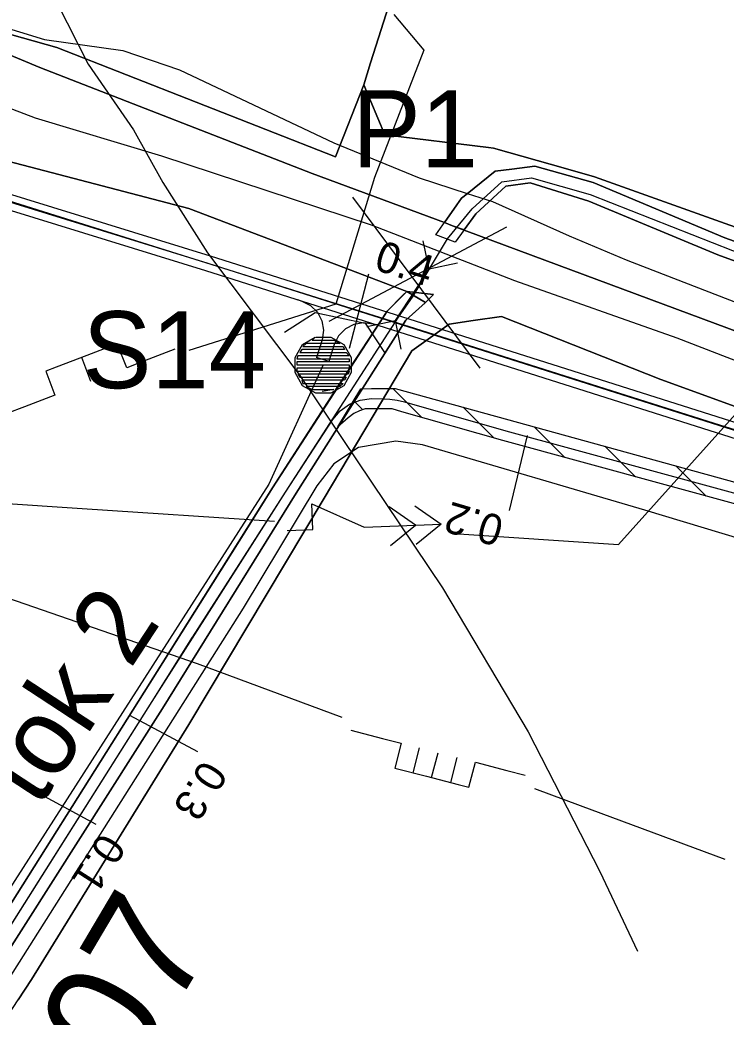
# Model space of a CAD drawing. Extents: x -645676 to -642474, y -1077513 to -1072613.
# Drawn here: x -645010.7 to -644873.3, y -1074904.3 to -1074710.1 of the extents above; entities that cross this region are included whole.
import ezdxf

# ---------------------------------------------------------------- set-up
doc = ezdxf.new("R2010")
doc.units = 0
for name, color, linetype in [('_elezni_n__tra_', 7, 'Continuous'), ('ELEKTRO', 7, 'Continuous'), ('KULTURY_STAV', 7, 'Continuous'), ('NOVY_STAV', 7, 'Continuous'), ('OSA', 7, 'Continuous'), ('PC_NAVRH', 7, 'Continuous'), ('PC_OBJ_POPIS_NAVRH', 7, 'Continuous'), ('PC_OBJ_POPIS_STAV', 7, 'Continuous'), ('PC_OBJEKTY_NAVRH', 7, 'Continuous'), ('PC_OBJEKTY_STAV', 7, 'Continuous'), ('PC_POPIS_NAVRH', 7, 'Continuous'), ('PC_STAN_NAVRH', 7, 'Continuous'), ('PLYNOVOD', 7, 'Continuous'), ('Ru_en__prvku_pr_zkumu', 7, 'Continuous'), ('SDELOVACI', 7, 'Continuous'), ('Vodn__plocha___navr_en_', 7, 'Continuous'), ('Vodn__plocha___st_vaj_c_', 7, 'Continuous'), ('Vodn__tok', 7, 'Continuous'), ('VRSTEVNICE', 7, 'Continuous')]:
    doc.layers.add(name, color=color, linetype=linetype)

# ---------------------------------------------------------------- blocks, each defined once
blk = doc.blocks.new('$406')
blk.add_lwpolyline([(-0.19, 0.72), (0.2, 0.72), (0.54, 0.53), (0.73, 0.19), (0.73, -0.2), (0.54, -0.54), (0.2, -0.73), (-0.19, -0.73), (-0.53, -0.54), (-0.72, -0.2), (-0.72, 0.19), (-0.53, 0.53), (-0.2, 0.72), (-0.28, 0.64), (0.28, 0.64), (0.44, 0.56), (-0.44, 0.56), (-0.52, 0.48), (0.52, 0.48), (0.56, 0.4), (-0.55, 0.4), (-0.6, 0.32), (0.6, 0.32), (0.68, 0.24), (-0.59, 0.24), (-0.65, 0.24), (-0.68, 0.16), (0.59, 0.16), (0.68, 0.16), (0.68, 0.08), (-0.59, 0.08), (-0.68, 0.08), (-0.68, 0), (0.59, 0), (0.68, 0), (0.68, -0.08), (-0.59, -0.08), (-0.68, -0.08), (-0.68, -0.16), (0.59, -0.16), (0.68, -0.16), (0.65, -0.24), (-0.62, -0.24), (-0.65, -0.24), (-0.6, -0.32), (0.6, -0.32), (0.56, -0.4), (-0.55, -0.4), (-0.52, -0.48), (0.52, -0.48), (0.44, -0.56), (-0.44, -0.56), (-0.28, -0.64), (0.28, -0.64), (-0.02, -0.69)])
blk = doc.blocks.new('$944')
blk.add_line((0, 1.5), (0, -1.5))
blk = doc.blocks.new('$938')
for p, q in [((-2, -0.8), (-1.2, 0)), ((2, -0.8), (1.2, 0))]:
    blk.add_line(p, q)
blk.add_lwpolyline([(-2, 0.8), (-1.2, 0), (1.2, 0), (2, 0.8)])
blk = doc.blocks.new('$935')
blk.add_lwpolyline([(-2, -1), (-1, 0), (1, 0), (2, -1)])
blk = doc.blocks.new('6$3320')
blk.add_line((0, 0), (0, -1))
blk.add_lwpolyline([(-3.5, 0), (-2.23, 0), (-1.5, 0), (-1.48, -1), (-0.21, -1), (1.06, -1), (1.5, -1), (1.5, 0), (2.77, 0), (3.5, 0)])
blk = doc.blocks.new('6$3520')
for p, q in [((-0.76, 0), (-0.76, -1)), ((0, -1), (0, 0)), ((0.76, 0), (0.76, -1))]:
    blk.add_line(p, q)
blk.add_lwpolyline([(-3.5, 0), (-2.23, 0), (-1.48, 0), (-1.48, -1), (-0.21, -1), (1.06, -1), (1.5, -1), (1.5, 0), (2.77, 0), (3.5, 0)])
blk = doc.blocks.new('6$6120')
for points in [[(-3, 0), (-2, 0), (-2, 1), (0, 0), (3, 0)], [(1, -0.75), (2, 0), (1, 0.75)], [(2, 0.75), (3, 0), (2, -0.75)]]:
    blk.add_lwpolyline(points)

msp = doc.modelspace()

# ---------------------------------------------------------------- linework, layer by layer
at = {"layer": '_elezni_n__tra_'}
msp.add_lwpolyline([(-645032.05, -1074719.88), (-645007.73, -1074729.17), (-644983.14, -1074736.55), (-644942.37, -1074750.02), (-644914.47, -1074760.84), (-644882.89, -1074772.03), (-644837.1, -1074789.71), (-644791.46, -1074806.27), (-644722.98, -1074831.82), (-644692.05, -1074843.35), (-644645.1, -1074860.33), (-644595.62, -1074879.05), (-644567.2, -1074889.68), (-644538.28, -1074900.75), (-644463.04, -1074928.93), (-644414.14, -1074947.15), (-644324.54, -1074980.78), (-644238.86, -1075012.25), (-644147.17, -1075045.91), (-644073.62, -1075073.69), (-644009.64, -1075097.37)], dxfattribs=at)
at = {"layer": 'ELEKTRO'}
for p, q in [((-644894.22, -1074812.25), (-644869.18, -1074784.33)), ((-645031.89, -1074803.02), (-644998.6, -1074805.22)), ((-644998.6, -1074805.22), (-644961.18, -1074807.74)), ((-644926.26, -1074810.09), (-644894.22, -1074812.25))]:
    msp.add_line(p, q, dxfattribs=at)
at = {"layer": 'KULTURY_STAV'}
for points in [[(-644709.44, -1074581.14), (-644730.58, -1074706.75), (-644732.72, -1074790.92), (-644735.42, -1074791.91), (-644740.74, -1074792.45), (-644752.88, -1074790.98), (-644762.52, -1074788.42), (-644782.83, -1074781.15), (-644828.75, -1074765.49), (-644872.55, -1074750.05), (-644898.87, -1074740.63), (-644904.54, -1074739.03), (-644918.57, -1074735.07), (-644919.51, -1074734.95), (-644939.69, -1074732.49), (-644943.82, -1074722.71), (-644942.47, -1074718.46), (-644938.39, -1074705.57), (-644930.04, -1074685.77), (-644963.2, -1074674.74), (-644974.18, -1074672.5), (-644977.8, -1074671.77), (-645004.38, -1074666.35), (-645021.55, -1074710.42)], [(-645004.38, -1074666.35), (-644977.8, -1074671.77), (-644974.18, -1074672.5), (-644963.2, -1074674.74), (-644930.04, -1074685.77), (-644938.39, -1074705.57), (-644942.47, -1074718.46), (-644943.82, -1074722.71), (-644949.33, -1074736.78), (-645003.54, -1074715.47), (-645021.55, -1074710.42), (-645004.38, -1074666.35)], [(-644739.24, -1074796.41), (-644741.21, -1074796.25), (-644753.29, -1074795.27), (-644763.22, -1074791.91), (-644783.72, -1074784.05), (-644829.59, -1074768.26), (-644873.51, -1074752.55), (-644899.17, -1074741.74), (-644910.48, -1074738.58), (-644914.98, -1074739.16), (-644918.25, -1074739.58), (-644923.71, -1074743.98), (-644924.76, -1074744.82), (-644925.66, -1074746.09), (-644928.12, -1074749.58), (-644953.82, -1074740.03), (-645006.81, -1074719.35), (-645042.1, -1074704.59)], [(-645042.1, -1074704.59), (-645006.81, -1074719.35), (-644953.82, -1074740.03), (-644928.12, -1074749.58), (-644926.53, -1074750.17), (-644824.29, -1074788.25), (-644721.17, -1074826.46), (-644584.34, -1074877.29), (-644564.38, -1074883.03)], [(-645021.55, -1074710.42), (-645003.54, -1074715.47), (-644949.33, -1074736.78), (-644943.82, -1074722.71), (-644939.69, -1074732.49), (-644919.51, -1074734.95), (-644918.57, -1074735.07), (-644904.54, -1074739.03), (-644898.87, -1074740.63), (-644872.55, -1074750.05), (-644828.75, -1074765.49), (-644782.83, -1074781.15), (-644762.52, -1074788.42), (-644752.88, -1074790.98), (-644740.74, -1074792.45), (-644735.42, -1074791.91)], [(-644564.38, -1074883.03), (-644584.34, -1074877.29), (-644721.17, -1074826.46), (-644824.29, -1074788.25), (-644926.53, -1074750.17), (-644924.29, -1074751), (-644921.99, -1074747.84), (-644916.18, -1074742.45), (-644911.44, -1074741.81), (-644900.01, -1074745.4), (-644874.88, -1074755.82), (-644831.04, -1074771.79), (-644785.45, -1074788.31), (-644764.37, -1074795.64), (-644750.56, -1074799.84), (-644748.99, -1074805.18), (-644738.03, -1074810.09), (-644717.25, -1074813.49), (-644716.55, -1074811.53), (-644714.76, -1074806.54), (-644714.21, -1074806.76), (-644727.89, -1074801.18), (-644630.29, -1074732.74)], [(-645015.85, -1074736.92), (-644977.85, -1074746.84), (-644935.44, -1074763.01), (-644936.11, -1074763.67), (-644939.27, -1074766.79), (-644961.54, -1074801.22), (-644966.95, -1074809.84), (-644986.51, -1074840.99), (-645018.72, -1074892.07)], [(-645014.97, -1074894.42), (-644983, -1074844.22), (-644956.94, -1074802.26), (-644935.62, -1074768.6), (-644931.83, -1074765.19), (-644931.8, -1074765.16), (-644935.44, -1074763.01), (-644977.85, -1074746.84), (-645015.85, -1074736.92)], [(-644732.46, -1074799.34), (-644742.26, -1074800.02), (-644748.85, -1074799.88), (-644750.56, -1074799.84), (-644764.37, -1074795.64), (-644785.45, -1074788.31), (-644831.04, -1074771.79), (-644874.88, -1074755.82), (-644900.01, -1074745.4), (-644911.44, -1074741.81), (-644916.18, -1074742.45), (-644921.99, -1074747.84), (-644924.29, -1074751), (-644926.53, -1074750.17), (-644928.12, -1074749.58), (-644925.66, -1074746.09), (-644924.76, -1074744.82), (-644923.71, -1074743.98), (-644918.25, -1074739.58), (-644914.98, -1074739.16), (-644910.48, -1074738.58)], [(-644910.48, -1074738.58), (-644899.17, -1074741.74), (-644873.51, -1074752.55), (-644829.59, -1074768.26), (-644783.72, -1074784.05), (-644763.22, -1074791.91), (-644753.29, -1074795.27), (-644741.21, -1074796.25), (-644739.24, -1074796.41)], [(-644935.44, -1074763.01), (-644931.8, -1074765.16), (-644931.83, -1074765.19), (-644935.62, -1074768.6), (-644956.94, -1074802.26), (-644983, -1074844.22), (-645014.97, -1074894.42), (-645017.72, -1074898.55), (-645018.93, -1074900.37), (-645044.44, -1074939.09), (-645045.86, -1074941.25), (-645068.03, -1074977.15), (-645070.41, -1074981), (-645083.41, -1075002.06), (-645100.26, -1075029), (-645115.32, -1075053.06), (-645110.92, -1075056.37), (-645106.23, -1075059.9), (-645101.51, -1075063.45), (-645100.28, -1075064.38), (-645087.88, -1075073.72), (-645083.47, -1075077.11), (-645066.84, -1075089.88)], [(-645018.72, -1074892.07), (-644986.51, -1074840.99), (-644966.95, -1074809.84), (-644961.54, -1074801.22), (-644939.27, -1074766.79), (-644936.11, -1074763.67), (-644935.44, -1074763.01)], [(-645066.84, -1075089.88), (-645083.47, -1075077.11), (-645087.88, -1075073.72), (-645100.28, -1075064.38), (-645101.51, -1075063.45), (-645106.23, -1075059.9), (-645110.92, -1075056.37), (-645107.37, -1075051.02), (-645078.58, -1075005), (-645065.05, -1074984.07), (-645062.6, -1074980.27), (-645037.32, -1074941.16), (-645011.04, -1074900.91), (-645008.49, -1074897.01), (-644977.86, -1074847.29), (-644951.5, -1074803.22), (-644934.42, -1074774.52), (-644927.17, -1074769.32), (-644922.5, -1074768.65), (-644917.01, -1074767.86)], [(-644571.94, -1074905.75), (-644582.1, -1074898.35), (-644587.88, -1074894.73), (-644599.15, -1074887.69), (-644603.1, -1074886.21), (-644625.37, -1074877.88), (-644648.69, -1074869.15), (-644694.81, -1074851.99), (-644725.16, -1074839.61), (-644735.7, -1074835.71), (-644794.33, -1074814.01), (-644839.75, -1074796.97), (-644886, -1074780.15), (-644917.01, -1074767.86), (-644922.5, -1074768.65), (-644927.17, -1074769.32), (-644934.42, -1074774.52), (-644951.5, -1074803.22), (-644977.86, -1074847.29), (-645008.49, -1074897.01), (-645011.04, -1074900.91)], [(-644917.01, -1074767.86), (-644886, -1074780.15), (-644839.75, -1074796.97), (-644794.33, -1074814.01), (-644735.7, -1074835.71), (-644725.16, -1074839.61), (-644694.81, -1074851.99), (-644648.69, -1074869.15), (-644625.37, -1074877.88), (-644599.15, -1074887.69), (-644587.88, -1074894.73), (-644582.1, -1074898.35), (-644571.94, -1074905.75)]]:
    msp.add_lwpolyline(points, dxfattribs=at)
at = {"layer": 'NOVY_STAV'}
for points in [[(-645338.95, -1074855.57), (-645302.15, -1074804.17), (-645264.81, -1074753.42), (-645236.22, -1074720.78), (-645204.21, -1074695.1), (-645184.64, -1074686.55), (-645169.47, -1074684.81), (-645164.45, -1074684.55), (-645159.43, -1074684.93), (-645154.51, -1074685.93), (-645143.42, -1074688.92), (-645139.79, -1074690.06), (-645136.27, -1074691.49), (-645132.87, -1074693.2), (-645092.84, -1074715.4), (-645051.12, -1074735.25), (-644974.57, -1074758.92), (-644816.15, -1074809.18), (-644755.54, -1074831.7), (-644751.49, -1074829.28), (-644747.27, -1074825.06)], [(-645050.03, -1074732.45), (-644973.68, -1074756.05), (-644815.17, -1074806.35), (-644765.11, -1074824.94), (-644764.76, -1074825.07), (-644764.42, -1074825.22), (-644764.08, -1074825.37), (-644763.37, -1074825.71), (-644760.1, -1074826.71), (-644756.68, -1074826.77), (-644753.37, -1074825.88), (-644750.45, -1074824.1), (-644750.16, -1074823.86), (-644747.27, -1074825.06)], [(-644956.68, -1074764.57), (-644955.83, -1074764.85), (-644954.15, -1074765.7), (-644952.82, -1074767.03), (-644951.95, -1074768.7), (-644951.64, -1074770.55), (-644951.91, -1074772.41), (-644952.98, -1074775.86)], [(-644941.37, -1074769.56), (-644941.98, -1074769.37), (-644943.84, -1074769.08), (-644945.71, -1074769.39), (-644947.38, -1074770.25), (-644948.71, -1074771.6), (-644949.55, -1074773.29), (-644950.6, -1074776.6), (-644952.98, -1074775.86)]]:
    msp.add_lwpolyline(points, dxfattribs=at)
at = {"layer": 'OSA'}
msp.add_lwpolyline([(-645035.91, -1074738.38), (-644974.13, -1074757.49), (-644815.66, -1074807.76), (-644760.32, -1074828.3), (-644757.44, -1074828.77), (-644756.51, -1074828.83), (-644755.59, -1074828.71), (-644754.7, -1074828.41), (-644752.08, -1074827.23), (-644749.02, -1074824.57), (-644746.07, -1074820.04)], dxfattribs=at)
at = {"layer": 'PC_NAVRH'}
for points in [[(-644567.19, -1074898.23), (-644579.49, -1074893.18), (-644609.51, -1074881.01), (-644677.32, -1074855.63), (-644745, -1074831.03), (-644754.83, -1074829.35), (-644791.71, -1074816.01), (-644820.96, -1074805.79), (-644875.57, -1074788.7), (-644932.63, -1074770.57), (-645017.52, -1074743.9), (-645048.97, -1074734.32), (-645061.39, -1074728.88), (-645092.58, -1074713.99), (-645134.64, -1074690.69), (-645139.68, -1074688.36), (-645154.82, -1074684.34), (-645162.37, -1074683.15), (-645179.59, -1074665.73)], [(-644951.73, -1074777.29), (-644962.3, -1074800.53), (-645034.31, -1074912.96), (-645109.61, -1075030.9)], [(-644726.92, -1074837.45), (-644730.08, -1074844.59), (-644733.42, -1074847.24), (-644737.78, -1074848.88), (-644742.64, -1074849.14), (-644775.59, -1074839.85), (-644889.12, -1074805.55), (-644932.37, -1074792.86), (-644937.59, -1074792.15), (-644944.85, -1074793.38), (-644949.65, -1074796.55), (-644952.92, -1074800.84), (-644967.24, -1074824.68), (-645035.16, -1074931.94), (-645112.98, -1075054.64)]]:
    msp.add_lwpolyline(points, dxfattribs=at)
at = {"layer": 'PLYNOVOD'}
for p, q in [((-644937.94, -1074709.02), (-644932.12, -1074715.98)), ((-644932.12, -1074715.98), (-644941.73, -1074740.8)), ((-644941.73, -1074740.8), (-644946.82, -1074757.6)), ((-644946.82, -1074757.6), (-644949.21, -1074765.46)), ((-644949.21, -1074765.46), (-644977.82, -1074774.49))]:
    msp.add_line(p, q, dxfattribs=at)
for points in [[(-645125.4, -1074747.22), (-645122.85, -1074748.19), (-645069.6, -1074769.43), (-645020.98, -1074788.06), (-645019.25, -1074788.72), (-645021.62, -1074819.73), (-644976.23, -1074835.43), (-644948.1, -1074845.86)], [(-644910.6, -1074859.76), (-644901.68, -1074863.07), (-644873.57, -1074873.56)]]:
    msp.add_lwpolyline(points, dxfattribs=at)
at = {"layer": 'Ru_en__prvku_pr_zkumu'}
for p, q in [((-644921.17, -1074777.92), (-644945.93, -1074744.61)), ((-644950.51, -1074768.75), (-644915.98, -1074750.41))]:
    msp.add_line(p, q, dxfattribs=at)
at = {"layer": 'SDELOVACI'}
msp.add_lwpolyline([(-645028.66, -1074706.96), (-645005.96, -1074713.92), (-644990.69, -1074716.08), (-644979.69, -1074719.8), (-644949.61, -1074734.04), (-644933, -1074740.83), (-644923.71, -1074743.9), (-644918.72, -1074745.46), (-644903.81, -1074752.12), (-644892.73, -1074756.82), (-644869.42, -1074765.85), (-644826.04, -1074782.12), (-644782.18, -1074798.29), (-644775.1, -1074800.98), (-644762.85, -1074806.13), (-644728.62, -1074818.48), (-644692.8, -1074831.01), (-644666.5, -1074840.69), (-644640.09, -1074850.4), (-644608.82, -1074862.69), (-644584.77, -1074871.19), (-644577.64, -1074873.63), (-644564.43, -1074876.66)], dxfattribs=at)
at = {"layer": 'Vodn__plocha___navr_en_'}
for p, q in [((-644932.47, -1074787.53), (-644938.13, -1074781.87)), ((-644943.98, -1074786.02), (-644945.73, -1074784.27)), ((-644918.48, -1074791.52), (-644924.48, -1074785.52)), ((-644904.69, -1074795.31), (-644910.67, -1074789.33)), ((-644890.94, -1074799.06), (-644896.87, -1074793.13)), ((-644877.18, -1074802.82), (-644883.06, -1074796.94))]:
    msp.add_line(p, q, dxfattribs=at)
for points in [[(-644948.82, -1074789.34), (-644944.34, -1074781.97), (-644942.28, -1074781.86), (-644940.21, -1074781.87), (-644937.72, -1074781.87), (-644836.28, -1074809.84)], [(-644837.4, -1074813.68), (-644916.71, -1074792.03), (-644936.42, -1074786.4), (-644938.28, -1074785.87), (-644940.21, -1074785.87), (-644942.28, -1074785.86), (-644943.51, -1074785.87), (-644944.61, -1074786.22), (-644945.71, -1074786.73), (-644946.85, -1074787.61), (-644948.82, -1074789.34), (-644944.34, -1074781.97), (-644942.28, -1074781.86), (-644940.21, -1074781.87), (-644937.72, -1074781.87), (-644836.28, -1074809.84)], [(-644837.4, -1074813.68), (-644916.71, -1074792.03), (-644936.42, -1074786.4), (-644938.28, -1074785.87), (-644940.21, -1074785.87), (-644942.28, -1074785.86), (-644943.51, -1074785.87), (-644944.61, -1074786.22), (-644945.71, -1074786.73), (-644946.85, -1074787.61), (-644948.82, -1074789.34), (-644944.34, -1074781.97), (-644942.28, -1074781.86), (-644940.21, -1074781.87), (-644937.72, -1074781.87), (-644836.28, -1074809.84)], [(-644837.4, -1074813.68), (-644916.71, -1074792.03), (-644936.42, -1074786.4), (-644938.28, -1074785.87), (-644940.21, -1074785.87), (-644942.28, -1074785.86), (-644943.51, -1074785.87), (-644944.61, -1074786.22), (-644945.71, -1074786.73), (-644946.85, -1074787.61), (-644948.82, -1074789.34)]]:
    msp.add_lwpolyline(points, dxfattribs=at)
at = {"layer": 'Vodn__plocha___st_vaj_c_'}
for points in [[(-644929.78, -1074751.93), (-644924.76, -1074744.82), (-644918.25, -1074739.58), (-644910.48, -1074738.58), (-644899.17, -1074741.74), (-644886.34, -1074747.14), (-644873.51, -1074752.55), (-644829.59, -1074768.26), (-644806.66, -1074776.16), (-644783.72, -1074784.05), (-644763.22, -1074791.91), (-644753.29, -1074795.27), (-644739.24, -1074796.41)], [(-644831.04, -1074771.79), (-644874.88, -1074755.82), (-644900.01, -1074745.4), (-644911.44, -1074741.81), (-644916.18, -1074742.45), (-644921.99, -1074747.84), (-644926.04, -1074753.4), (-644929.78, -1074751.93), (-644924.76, -1074744.82), (-644918.25, -1074739.58), (-644910.48, -1074738.58), (-644899.17, -1074741.74), (-644886.34, -1074747.14), (-644873.51, -1074752.55), (-644829.59, -1074768.26)], [(-644732.93, -1074799.15), (-644742.26, -1074800.02), (-644750.56, -1074799.84), (-644764.37, -1074795.64), (-644785.45, -1074788.3), (-644831.04, -1074771.79), (-644874.88, -1074755.82), (-644900.01, -1074745.4), (-644911.44, -1074741.81), (-644916.18, -1074742.45), (-644921.99, -1074747.84), (-644926.04, -1074753.4), (-644929.78, -1074751.93)], [(-644930.24, -1074763.57), (-644931.8, -1074765.16), (-644935.62, -1074768.6), (-644956.94, -1074802.26), (-644983, -1074844.22), (-645014.97, -1074894.42), (-645018.93, -1074900.37), (-645022.65, -1074897.92), (-645018.72, -1074892.07), (-644986.51, -1074840.99), (-644961.54, -1074801.22), (-644949, -1074781.71), (-644939.27, -1074766.79), (-644935.44, -1074763.01), (-644930.24, -1074763.57)]]:
    msp.add_lwpolyline(points, dxfattribs=at)
msp.add_lwpolyline([(-644930.24, -1074763.57), (-644935.44, -1074763.01), (-644939.27, -1074766.79), (-644949, -1074781.71), (-644961.54, -1074801.22), (-644986.51, -1074840.99), (-645018.72, -1074892.07), (-645022.65, -1074897.92), (-645018.93, -1074900.37), (-645014.97, -1074894.42), (-644983, -1074844.22), (-644956.94, -1074802.26), (-644935.62, -1074768.6), (-644931.8, -1074765.16)], close=True, dxfattribs=at)
at = {"layer": 'Vodn__tok'}
for points in [[(-645118.46, -1075054.04), (-645116, -1075050.01), (-645085.27, -1075000.55), (-645046.98, -1074940.37), (-645020.72, -1074899.28), (-645016.84, -1074893.24), (-644984.96, -1074842.87), (-644959.03, -1074802.05), (-644937.04, -1074767.99), (-644934.18, -1074763.89), (-644927.51, -1074752.73), (-644922.7, -1074746.9), (-644916.92, -1074741.6), (-644911.15, -1074740.87), (-644899.76, -1074744.07), (-644872.06, -1074754.98), (-644827.55, -1074771.19), (-644782.23, -1074787.3), (-644761.55, -1074794.86), (-644753.14, -1074797.12), (-644740.1, -1074798.4), (-644731, -1074797.09)], [(-645016.79, -1074893.16), (-644984.95, -1074842.87), (-644977.1, -1074830.34), (-644977.08, -1074830.31), (-644977.06, -1074830.28), (-644977.04, -1074830.25), (-644959.03, -1074802.05), (-644949.84, -1074787.95), (-644948.39, -1074786.25), (-644946.58, -1074784.95), (-644944.49, -1074784.14), (-644942.28, -1074783.86), (-644940.21, -1074783.87), (-644938.75, -1074783.93), (-644937.3, -1074784.14), (-644935.87, -1074784.47), (-644916.18, -1074790.1), (-644836.84, -1074811.76)]]:
    msp.add_lwpolyline(points, dxfattribs=at)
at = {"layer": 'VRSTEVNICE'}
msp.add_lwpolyline([(-645027.05, -1074648.91), (-645009.67, -1074694.48), (-644997.43, -1074718.69), (-644988.6, -1074731.51), (-644982.9, -1074741.76), (-644974.21, -1074755.44), (-644956.27, -1074779.36), (-644928.49, -1074820.67), (-644911.83, -1074848.72), (-644897.87, -1074875.93), (-644890.53, -1074891.49)], dxfattribs=at)

# ---------------------------------------------------------------- block references
at = {"layer": 'ELEKTRO', "xscale": 5, "yscale": 5, "rotation": 2.367209}
msp.add_blockref('6$6120', (-644943.72, -1074808.91), dxfattribs=at)
at = {"layer": 'PC_OBJEKTY_NAVRH', "xscale": 5, "yscale": 4.999999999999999, "rotation": -12.032500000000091}
msp.add_blockref('$935', (-644948.4, -1074768.12), dxfattribs=at)
at = {"layer": 'PC_OBJEKTY_STAV', "xscale": 5, "yscale": 5, "rotation": 56.780088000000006}
msp.add_blockref('$938', (-644934.36, -1074763.65), dxfattribs=at)
at = {"layer": 'PC_STAN_NAVRH'}
for p, xscale, yscale, rotation in [((-644944.68, -1074766.78), 5, 5, 165.396781), ((-644913.66, -1074798.35), 4.999999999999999, 5.000000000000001, 166.510242), ((-644982.71, -1074849.11), 5, 5, -118.19493), ((-645002.46, -1074863.24), 5.000000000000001, 5, -118.498063)]:
    msp.add_blockref('$944', p, dxfattribs=dict(at, xscale=xscale, yscale=yscale, rotation=rotation))
at = {"layer": 'PC_STAN_NAVRH', "xscale": 7.5, "yscale": 7.5}
msp.add_blockref('$406', (-644951.73, -1074777.29), dxfattribs=at)
at = {"layer": 'PLYNOVOD'}
for name, p, xscale, yscale, rotation in [('6$3320', (-644996.89, -1074780.51), 5, 5, -159.03202800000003), ('6$3520', (-644929.35, -1074852.81), 5.000000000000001, 5.000000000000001, -14.414531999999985)]:
    msp.add_blockref(name, p, dxfattribs=dict(at, xscale=xscale, yscale=yscale, rotation=rotation))

# ---------------------------------------------------------------- texts
at = {"layer": 'PC_OBJ_POPIS_NAVRH'}
msp.add_text('S14', height=15, dxfattribs=at).set_placement((-644998.5, -1074781.83))
at = {"layer": 'PC_OBJ_POPIS_STAV'}
msp.add_text('P1', height=15, dxfattribs=at).set_placement((-644946.08, -1074738.8))
at = {"layer": 'PC_POPIS_NAVRH'}
msp.add_text('C 07', height=22, rotation=59.416, dxfattribs=at).set_placement((-645004.23, -1074942.82))
at = {"layer": 'PC_STAN_NAVRH'}
for s, rotation, p in [('0.4', 341.999, (-644942.04, -1074758.63)), ('0.2', 163.637, (-644916.19, -1074806.99)), ('0.3', 237.663, (-644975.1, -1074853.92)), ('0.1', 237.376, (-644994.88, -1074868.09))]:
    msp.add_text(s, height=6, rotation=rotation, dxfattribs=at).set_placement(p)
at = {"layer": 'Vodn__tok'}
msp.add_text('tok 2', height=15, rotation=56.723, dxfattribs=at).set_placement((-645007, -1074863.73))

doc.saveas('drawing.dxf')
